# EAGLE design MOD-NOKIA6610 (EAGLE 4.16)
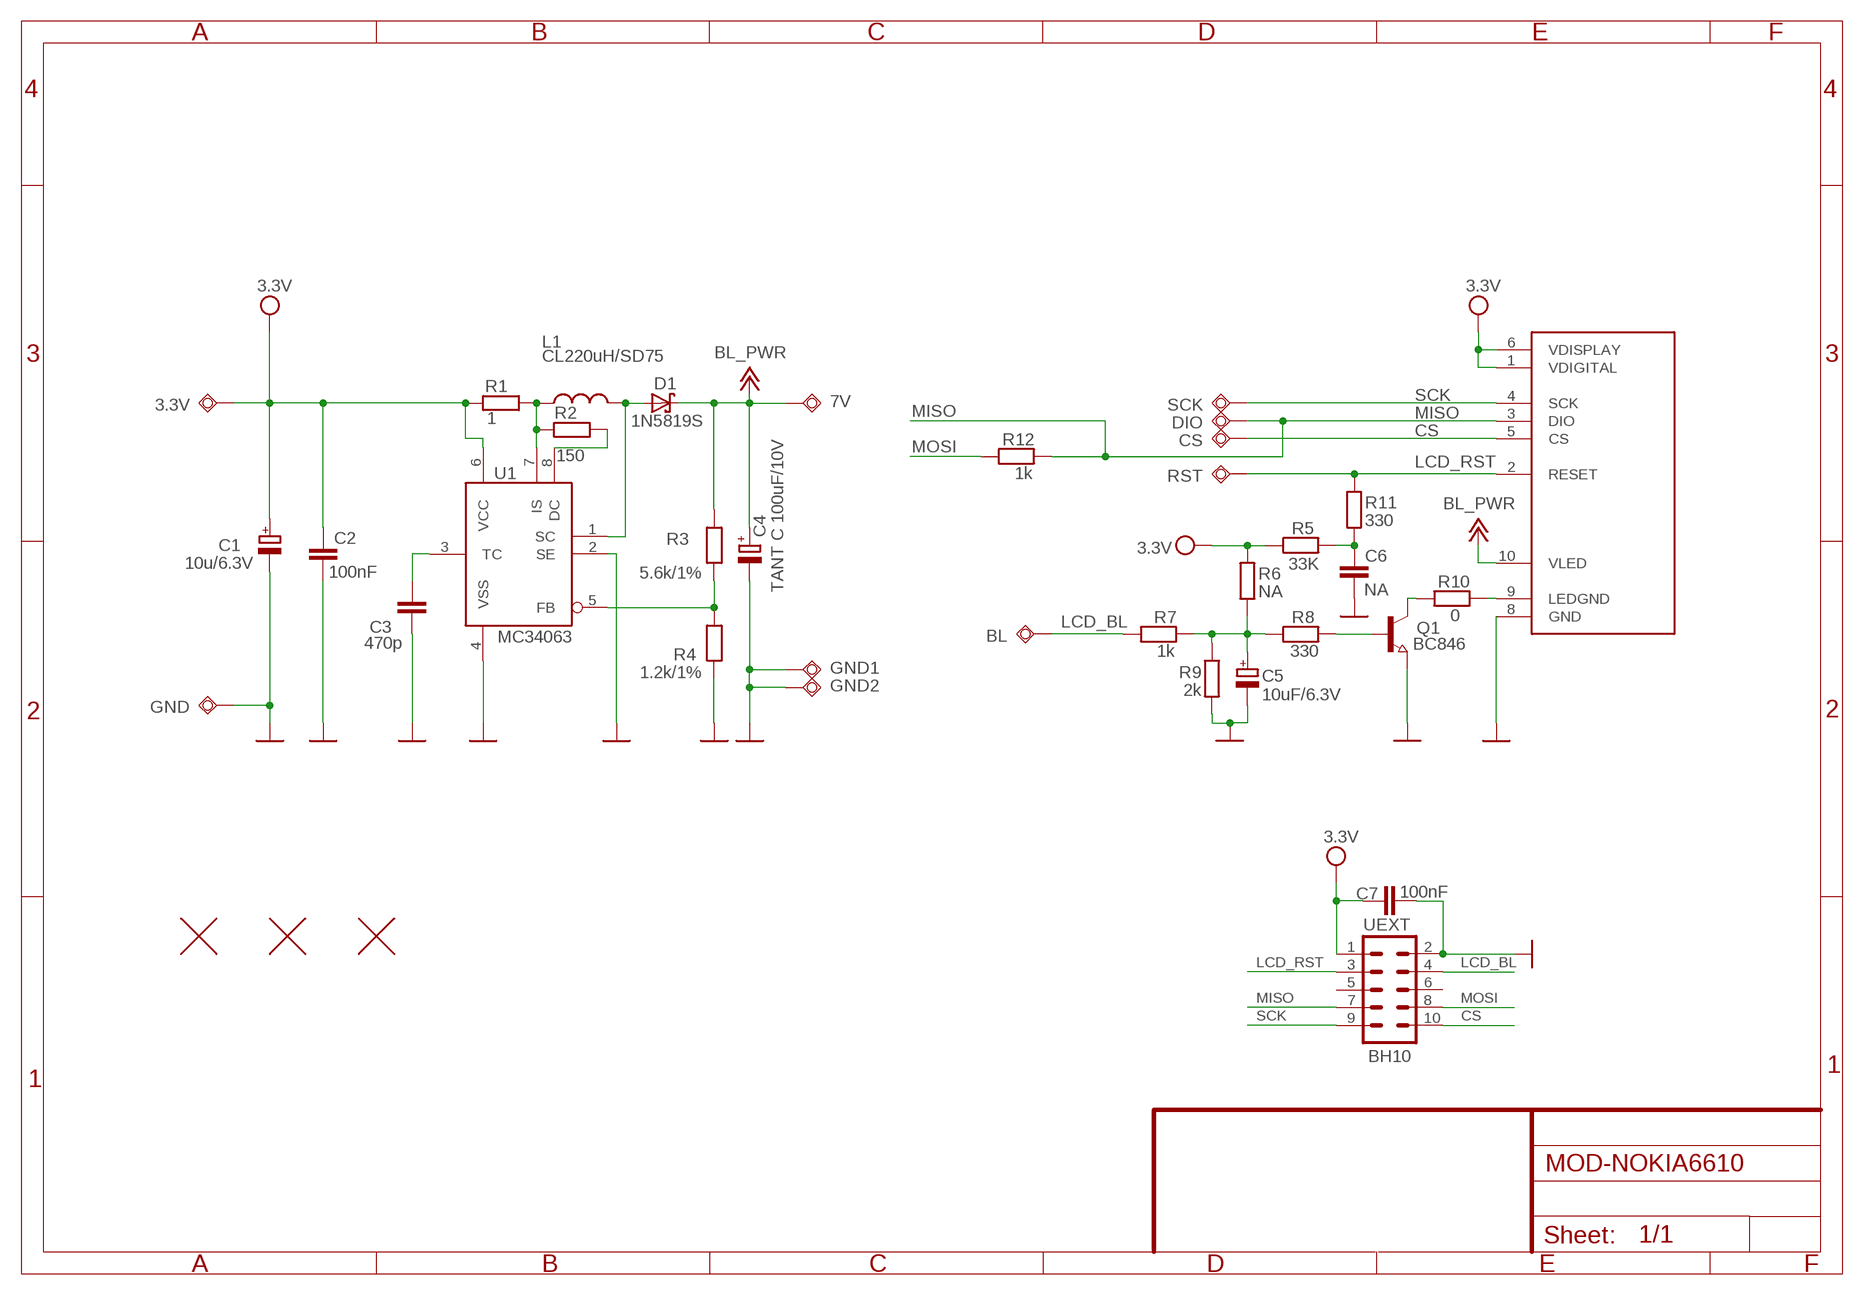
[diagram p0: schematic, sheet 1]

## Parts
3.3V  TESTPAD3  [TEST_PAD40/70/SQUARE]
7V  TESTPAD40/70  [TESTPAD]
BL  TESTPAD40/70  [TESTPAD]
C1  10u/6.3V  CPOL_S  [CT3216_PLUS]
C2  100nF  C_0805  [0805]
C3  470p  C_0805  [0805]
C4  TANT C 100uF/10V  CPOL-EUCT7343  [CT7343]
C5  10uF/6.3V  CPOL_S  [CT3216_PLUS]
C6  NA  C_0805  [0805]
C7  100nF  C_0805  [0805]
CS  TESTPAD40/70  [TESTPAD]
D1  1N5819S  SCHOTKKY7.62SS2  [MLL-41]
DIO  TESTPAD40/70  [TESTPAD]
GND  TESTPAD40/70  [TESTPAD]
GND1  TESTPAD40/70  [TESTPAD]
GND2  TESTPAD40/70  [TESTPAD]
L1  CL220uH/SD75  LCLXXUH_SD73  [CLXXUH_SD73]
LCD  NOKIA6610_COLOR_LCD  NOKIA6100_LCD  [NOKIA6100_LCD]
Q1  BC846  NPN-TRANSISTOR_SOT23  [SOT23]
R1  1  R_0805  [0805]
R2  150  R_0805  [0805]
R3  5.6k/1%  R_0805  [0805]
R4  1.2k/1%  R_0805  [0805]
R5  33K  R_0805  [0805]
R6  NA  R_0805  [0805]
R7  1k  R_0805  [0805]
R8  330  R_0805  [0805]
R9  2k  R_0805  [0805]
R10  0  R_0805  [0805]
R11  330  R_0805  [0805]
R12  1k  R_0805  [0805]
RST  TESTPAD40/70  [TESTPAD]
SCK  TESTPAD40/70  [TESTPAD]
U1  MC34063  MC34063A2  [SO-8]
U$5  FIDUCIAL1X2  [FIDUCIAL-1X2]
U$6  FIDUCIAL1X2  [FIDUCIAL-1X2]
U$7  FIDUCIAL1X2  [FIDUCIAL-1X2]
UEXT  BH10  ML10SMD  [ML10_PADS]

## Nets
7.1V: 7V.P$1(PP) C4.+ D1.K(C) LCD.10(VLED) R3.P$2 ; supply symbol labelled BL_PWR
CS: CS.P$1(PP) LCD.5(CS) UEXT.10
GND: C1.-1(-) C2.P$2 C3.P$2 C4.- C5.-1(-) C6.P$2 C7.P$2 GND1.P$1(PP) GND2.P$1(PP) GND.P$1(PP) LCD.8(GND) Q1.2(E) R4.P$1 R9.P$2 U1.2(SE) U1.4(VSS) UEXT.2
LCD_BL: BL.P$1(PP) R7.P$1 UEXT.4
LCD_RST: LCD.2(RESET) R11.P$2 RST.P$1(PP) UEXT.3
MISO: DIO.P$1(PP) LCD.3(DIO) R12.P$2 UEXT.7
MOSI: R12.P$1 UEXT.8
N$1: C6.P$1 R5.P$1 R11.P$1
N$137: R3.P$1 R4.P$2 U1.5(FB)
N$138: C3.P$1 U1.3(TC)
N$139: D1.A L1.2 U1.1(SC)
N$140: LCD.9(LEDGND) R10.P$2
N$141: C5.+1(+) R6.P$1 R7.P$2 R8.P$1 R9.P$1
N$142: Q1.3(C) R10.P$1
N$143: Q1.1(B) R8.P$2
N$144: L1.1 R1.P$2 R2.P$1 U1.7(IS)
N$145: R2.P$2 U1.8(DC)
SCK: LCD.4(SCK) SCK.P$1(PP) UEXT.9
VCC: 3.3V.P$1(PP) C1.+1(+) C2.P$1 C7.P$1 LCD.1(VDIGITAL) LCD.6(VDISPLAY) R1.P$1 R5.P$2 R6.P$2 U1.6(VCC) UEXT.1 ; supply symbol labelled 3.3V
Unconnected: UEXT.5 UEXT.6

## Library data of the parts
3.3V 7V BL CS DIO GND GND1 GND2 RST SCK = gogo:TESTPAD: drill 40mils, diameter 70mils
C1 C5 = ivan:CPOL_?
C2 C3 C6 C7 = 1:C_?
C4 = rcl:CPOL-EU: POLARIZED CAPACITOR, European symbol
D1 = gogo:SCHOTKKY7.62SS
L1 = DOUBLE-SIDE:L
LCD = nokia_6100:NOKIA6100_LCD
Q1 = semicon-smd-ipc:NPN-TRANSISTOR_: NPN TRANSISTOR
R1-R12 = ivan:R_?
U1 = MPLAB_ICD2:MC34063A
U$5-U$7 = SparkFunEagle-6-6-07:FIDUCIAL: Fiducial Alignment Points
UEXT = con-harting-ml:ML10: HARTING

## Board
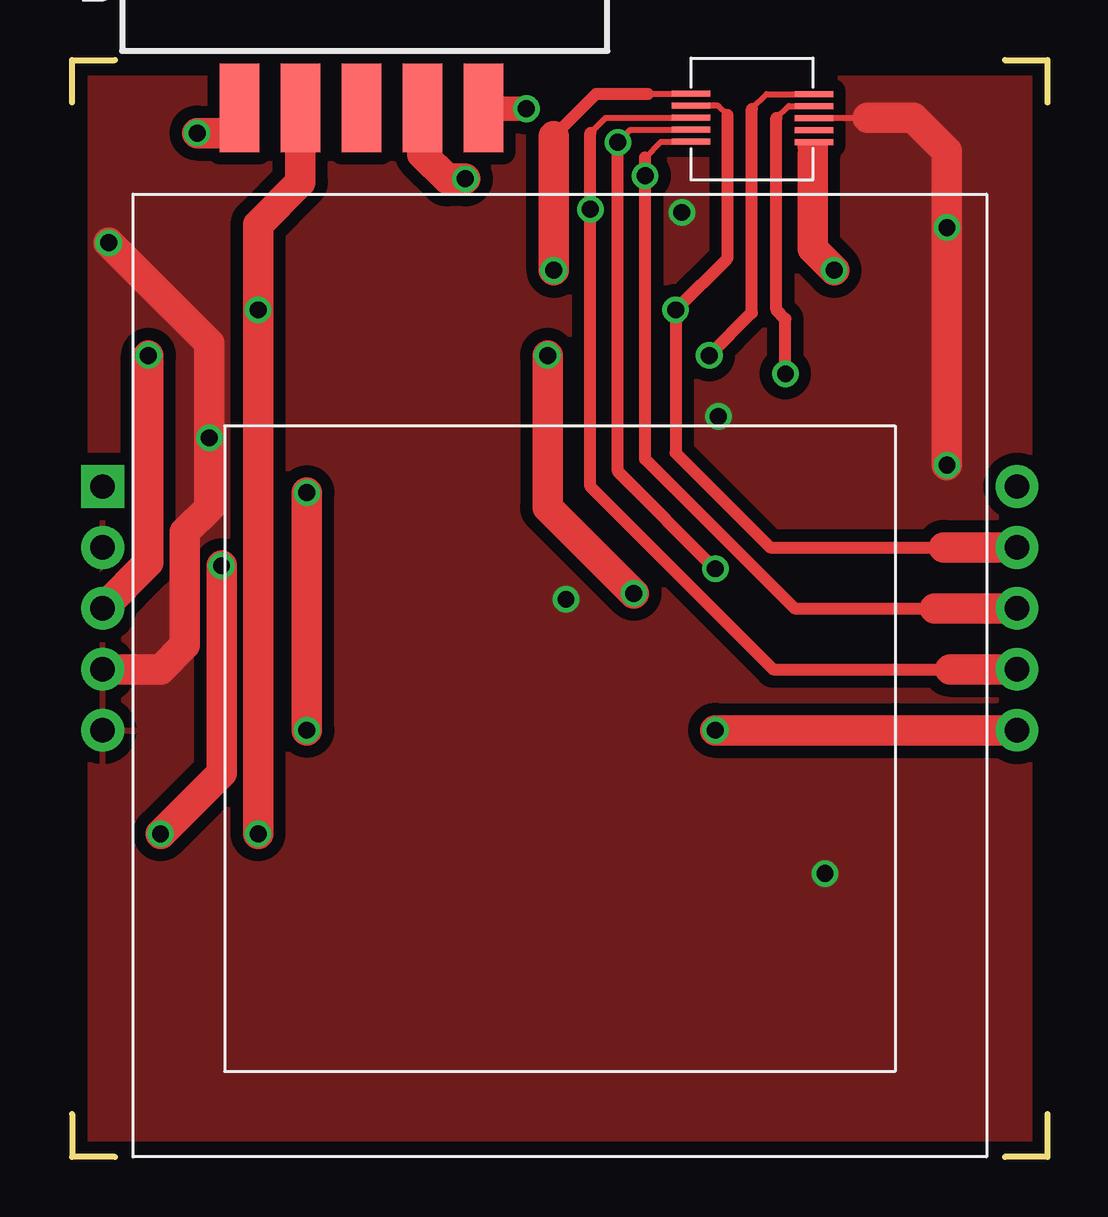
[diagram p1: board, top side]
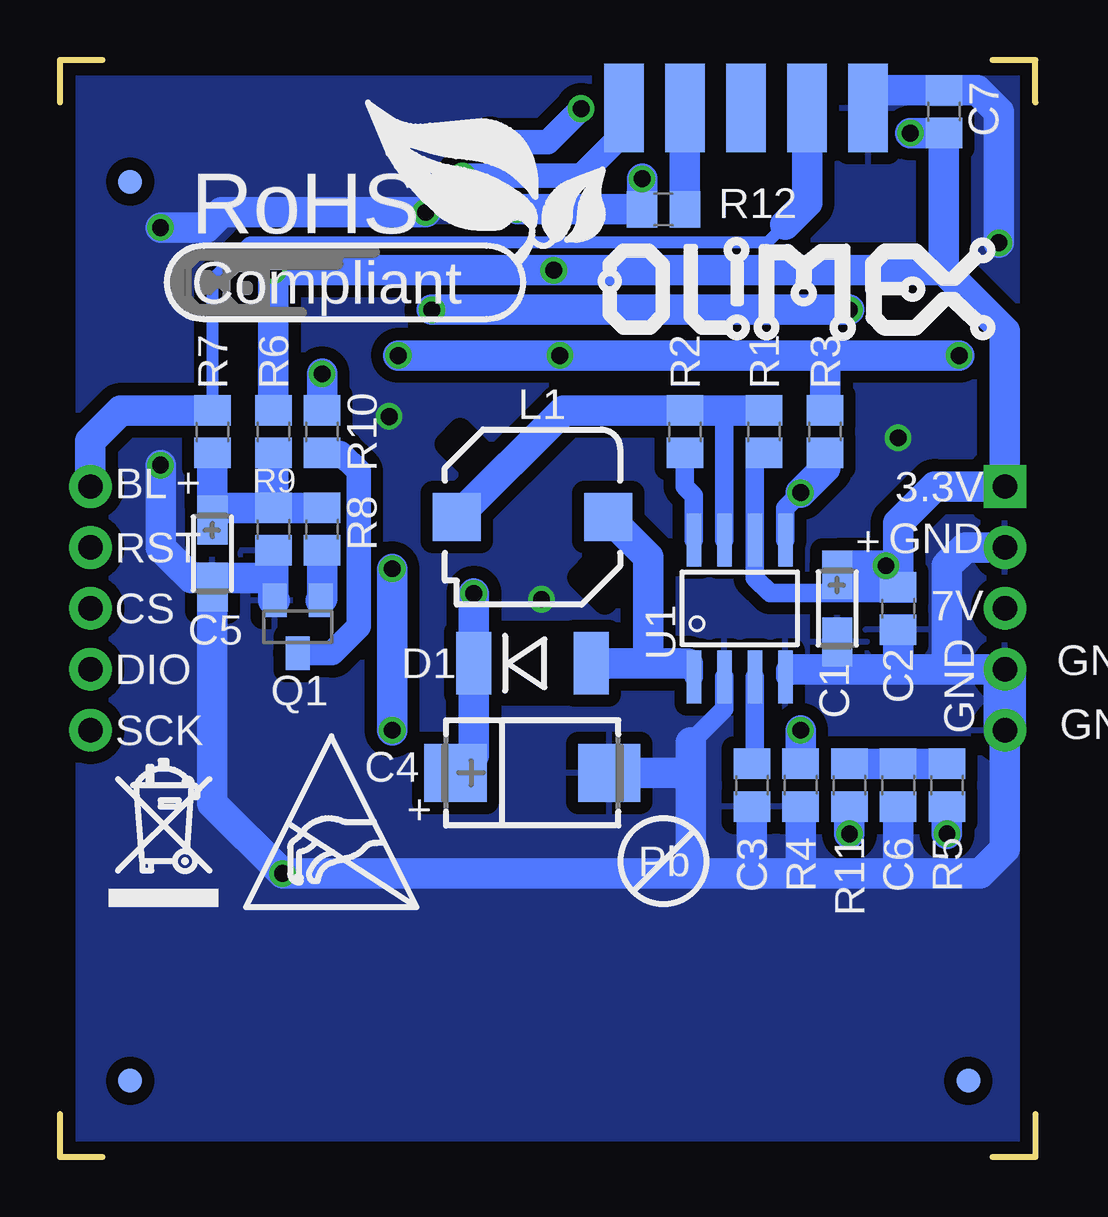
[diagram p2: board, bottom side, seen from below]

Size 40.64 x 45.72 mm. Coordinates in mm from the lower left corner, seen from the top.
Outline: 1.78,45.72 0,45.72 0,43.94
Outline: 38.86,45.72 40.64,45.72 40.64,43.94
Outline: 40.64,1.78 40.64,0 38.86,0
Outline: 1.78,0 0,0 0,1.78
Copper layers (1*16): Top 0.035mm / dielectric 1.5mm / Bottom 0.035mm
Design rules "default": minimum track width 10mil, minimum drill 23mil, track to track 9.5mil, track to pad 9.5mil, pad to pad 9.5mil, via to via 10mil, smd to smd 0mil, copper to edge 10mil, drill to drill 8mil, minimum pad ring 10mil, minimum via ring 8mil, stop-mask expansion 4mil, vias tented up to drill 28mil, thermal gap 20mil
tRestrict: 4 lines
bRestrict: 4 lines

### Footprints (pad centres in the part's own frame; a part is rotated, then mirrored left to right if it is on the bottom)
TEST_PAD40/70/SQUARE = drill 1.016 pad 1.778 square: P$1 0,0
TESTPAD = drill 1.016 pad 1.778 round: P$1 0,0
CT3216_PLUS = smd 2.032 x 1.27: +1 -1.397,0; -1 1.397,0
0805 = smd 1.27 x 1.524: P$1 -0.889,0; P$2 0.889,0
CT7343 = smd 2.6 x 2.4: + -3.2,0; - 3.2,0
MLL-41 = smd 1.45 x 2.6: A 2.445,0; K -2.445,0
CLXXUH_SD73 = smd 2 x 2: 1 0,3.15; 2 0,-3.15
NOKIA6100_LCD = smd 1.6 x 0.25: 1 24.255,44.311; 2 24.255,43.811; 3 24.255,43.311; 4 24.255,42.811; 5 24.255,42.311; 6 29.389,42.303; 7 29.389,42.803; 8 29.389,43.303; 9 29.389,43.803; 10 29.389,44.303
SOT23 = smd 1 x 1.4: 1 -0.95,-1.1; 2 0.95,-1.1; 3 0,1.1
SO-8 = smd 0.6 x 2.2: 1 -1.905,-2.854; 2 -0.635,-2.854; 3 0.635,-2.854; 4 1.905,-2.854; 5 1.905,2.854; 6 0.635,2.854; 7 -0.635,2.854; 8 -1.905,2.854
FIDUCIAL-1X2 = smd 1 x 1: 1 0,0
ML10_PADS = smd 1.651 x 3.683: 1 -5.093,-0.229; 3 -2.553,-0.229; 5 -0.013,-0.229; 7 2.527,-0.229; 9 5.067,-0.229 | smd 1.651 x 3.683 bottom: 2 -5.093,-0.229; 4 -2.553,-0.229; 6 -0.013,-0.229; 8 2.527,-0.229; 10 5.067,-0.229

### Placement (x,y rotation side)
3.3V  1.27,27.94 0 top
7V  1.27,22.86 0 top
BL  39.37,27.94 0 top
C1  8.25,22.86 270 bottom
C2  5.71,22.86 270 bottom
C3  11.81,15.49 270 bottom
C4  20.96,16 0 bottom
C5  34.29,25.15 270 bottom
C6  5.71,15.49 270 bottom
C7  3.81,43.56 90 bottom
CS  39.37,22.86 0 top
D1  20.96,20.57 0 bottom
DIO  39.37,20.32 0 top
GND  1.27,25.4 0 top
GND1  1.27,20.32 0 top
GND2  1.27,17.78 0 top
L1  20.96,26.67 90 bottom
LCD  1.52,0 0 top
Q1  30.73,22.1 180 bottom
R1  11.3,30.23 90 bottom
R2  14.61,30.23 270 bottom
R3  8.76,30.23 90 bottom
R4  9.78,15.49 90 bottom
R5  3.68,15.49 270 bottom
R6  31.75,30.23 90 bottom
R7  34.29,30.23 270 bottom
R8  29.72,26.16 270 bottom
R9  31.75,26.16 270 bottom
R10  29.72,30.23 90 bottom
R11  7.75,15.49 270 bottom
R12  15.49,39.5 180 bottom
RST  39.37,25.4 0 top
SCK  39.37,17.78 0 top
U1  12.32,22.86 0 bottom
U$1  [PB_SMALL]  15.49,12.32 0 bottom
U$2  [RECYCLE_BIN1/8]  38.61,10.41 0 bottom
U$3  [ESD_SYMBOL]  32.89,10.41 0 bottom
U$4  [ROHS]  35.18,35.56 0 bottom
U$5  37.72,40.64 0 bottom
U$6  37.72,3.17 0 bottom
U$7  2.79,3.17 0 bottom
U$8  [OLIMEX1_V]  0.51,33.91 0 bottom
UEXT  12.06,43.94 0 top

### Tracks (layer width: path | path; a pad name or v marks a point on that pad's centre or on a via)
7.1V  (via drill 0.7)
  Top 0.254: LCD.10 28.94,44.3 28.32,43.69
  Top 0.508: 28.32,43.69 28.32,35.18 v26.54,33.4
  Top 1.27: 7V.P$1 3.17,24.77 v3.17,33.4 | v23.4,23.48 19.81,27.07 v19.81,33.4
  Bottom 1.27: 8.76,33.4 R3.P$2 | 8.76,33.4 v19.81,33.4 v26.54,33.4 | v3.17,33.4 8.76,33.4 | 23.4,17.78 D1.K | v23.4,23.48 23.4,17.78 | 23.4,17.78 23.4,16.73 24.13,16 C4.+
CS  (via drill 0.7)
  Top 0.254: LCD.5 24.53,42.31 23.88,41.66
  Top 0.508: 35.94,22.86 30.1,22.86 23.88,29.08 v23.88,40.89 23.88,41.66
  Top 1.27: 35.94,22.86 CS.P$1
  Bottom 1.016: UEXT.10 17.13,42.69 18.92,40.89 v23.88,40.89
GND  (via drill 0.7)
  Top 0.254: LCD.8 33.15,43.3 33.15,43.31
  Top 1.27: GND1.P$1 3.68,20.32 4.7,21.34 4.7,26.04 5.71,27.05 v5.71,29.97 5.71,33.91 v1.52,38.1 | v36.45,28.83 v36.45,38.73 36.45,41.91 35.05,43.31 33.15,43.31
  Bottom 0.762: U1.4 10.41,20.32 10.16,20.32 | U1.2 12.95,18.67 14.35,17.27
  Bottom 1.27: GND1.P$1 3.68,20.32 | 3.68,20.32 5.71,20.32 | 5.71,20.32 C2.P$2 | 8.25,20.32 C1.-1 | 5.71,20.32 8.25,20.32 | 8.25,20.32 10.16,20.32 | 14.35,16 14.35,17.27 | GND.P$1 2.92,25.4 3.68,24.64 3.68,20.32 | GND2.P$1 1.27,12.83 2.29,11.81 5.71,11.81 | 14.35,16 C4.- | 34.29,24.13 31.75,24.13 | 31.75,24.13 R9.P$2 | Q1.2 31.75,23.2 31.75,24.13 | 5.71,11.81 9.78,11.81 | 9.78,11.81 11.81,11.81 | 11.81,11.81 14.35,11.81 | 14.35,11.81 14.35,16 | 5.71,11.81 C6.P$2 | 9.78,11.81 R4.P$1 | 11.81,11.81 C3.P$2 | 14.35,11.81 v31.37,11.81 34.29,14.73 C5.-1 34.29,24.13 | v36.45,28.83 36.45,25.4 35.18,24.13 34.29,24.13 | UEXT.2 6.97,44.45 C7.P$2 2.41,44.45 1.52,43.56 v1.52,38.1 | v36.45,38.73 34.54,38.73 33.91,39.37 v25.4,39.37
  Bottom 1.778: GND2.P$1 GND1.P$1
  other vias: 26.92,30.86 20.57,23.24
  pour Bottom (isolate 0.508): -1.02,45.72 42.16,45.72 42.16,-1.27 -1.02,-1.27
  pour Top (isolate 0.508): -1.02,45.72 21.84,45.72 42.16,45.72 42.16,-1.27 -1.02,-1.27
LCD_BL
  Bottom 0.508: 10.41,38.86 11.18,38.1 32.77,38.1 34.29,36.58 R7.P$1
  Bottom 1.27: BL.P$1 39.37,29.84 38.1,31.11 R7.P$1 | UEXT.4 9.51,39.76 10.41,38.86
LCD_RST  (via drill 0.7)
  Top 0.254: LCD.2 26.93,43.81 27.3,43.43
  Top 0.508: 27.3,43.43 27.3,37.47 v25.15,35.31 25.15,29.34 29.08,25.4 36.32,25.4
  Top 1.27: v7.75,13.46 v7.75,35.31 7.75,38.86 9.51,40.63 UEXT.3 | 36.32,25.4 RST.P$1
  Bottom 1.27: v7.75,35.31 v25.15,35.31 | R11.P$2 v7.75,13.46
MISO  (via drill 0.7)
  Top 0.254: LCD.3 22.23,43.31 21.59,42.67
  Top 0.508: 21.59,42.67 v21.59,39.5 21.59,27.94 29.21,20.32 36.58,20.32
  Top 1.27: 36.58,20.32 DIO.P$1 | UEXT.7 14.59,41.8 15.62,40.77 v16.38,40.77
  Bottom 1.27: v16.38,40.77 R12.P$2 v21.59,39.5
MOSI
  Bottom 1.27: UEXT.8 14.61,43.71 R12.P$1
N$1
  Bottom 1.27: R5.P$1 C6.P$1 R11.P$1
N$137  (via drill 0.7)
  Top 1.27: v9.78,17.78 v9.78,27.69
  Bottom 0.762: v9.78,27.69 10.41,27.05 U1.5
  Bottom 1.27: v9.78,27.69 8.76,28.7 R3.P$1 | R4.P$2 v9.78,17.78
N$138
  Bottom 0.762: C3.P$1 11.81,16.51 11.68,16.64 U1.3
N$139
  Bottom 0.762: U1.1 14.22,20.57 14.48,20.57
  Bottom 1.27: 14.48,20.57 16.13,20.57 | 16.13,20.57 D1.A | L1.2 16.13,24.99 16.13,20.57
N$140  (via drill 0.7)
  Top 0.254: LCD.9 29.86,43.8 29.34,43.28 29.34,43.31
  Top 0.508: v29.72,32.64 29.72,34.92 29.34,35.31 29.34,43.31
  Bottom 1.27: R10.P$2 v29.72,32.64
N$141
  Bottom 1.27: R8.P$1 R9.P$1 | R9.P$1 R6.P$1 | 34.29,27.05 C5.+1 | R9.P$1 34.29,27.05 | 34.29,27.05 R7.P$2
N$142
  Bottom 1.016: R10.P$1 28.96,29.34 28.19,28.57 28.19,22.1 29.29,21 Q1.3
N$143
  Bottom 1.27: Q1.1 29.72,23.26 R8.P$2
N$144
  Bottom 0.762: U1.7 12.95,31.11
  Bottom 1.27: R1.P$2 12.95,31.11 R2.P$1 19.66,31.11 L1.1
N$145
  Bottom 0.762: U1.8 14.22,27.56 14.61,27.94 R2.P$2
SCK  (via drill 0.7)
  Top 0.254: LCD.4 23.25,42.81 v22.73,42.29
  Top 0.508: v22.73,42.29 22.73,28.57 v26.8,24.51
  Top 1.016: UEXT.9 17.16,43.69 v18.92,43.69
  Top 1.27: v26.8,17.78 SCK.P$1
  Bottom 1.016: v22.73,42.29 20.32,42.29 v18.92,43.69
  Bottom 1.27: v26.8,17.78 v26.8,24.51
VCC  (via drill 0.7)
  Top 0.254: 23.99,44.31 LCD.1 | LCD.6 30.35,42.3 30.35,42.04 30.86,42.04 30.86,42.29 31.37,42.29 31.37,41.78 30.86,41.78
  Top 0.508: 20.07,42.55 21.83,44.31 23.99,44.31
  Top 1.27: v3.68,13.46 6.22,16 v6.22,24.64 | v31.75,36.96 30.86,37.85 30.86,41.78 | v20.07,36.96 20.07,42.55 | UEXT.1 6.97,42.67 v5.21,42.67
  Bottom 0.762: 8.25,23.75 8.25,23.5 11.05,23.5 11.68,24.13 U1.6 11.68,29.34 R1.P$1
  Bottom 1.27: 5.71,24.64 C2.P$1 8.25,23.75 8.25,24.64 | 5.71,24.64 v6.22,24.64 8.25,24.64 | 5.71,24.64 5.71,26.42 4.19,27.94 3.3V.P$1 1.27,34.42 3.81,36.96 | 8.25,24.64 7.37,24.64 | 8.25,24.64 C1.+1 | R5.P$2 v3.68,13.46 | 3.81,36.96 v20.07,36.96 v31.75,36.96 R6.P$2 | v5.21,42.67 C7.P$1 3.81,36.96

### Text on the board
bNames: + | + | +
tStop: REV. B | (C) 2009 | LCD NOKIA 6610 | WWW.OLIMEX.COM
bStop: Rev. B | WWW.OLIMEX.COM/DEV | (C) 2009 | LCD NOKIA 6610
